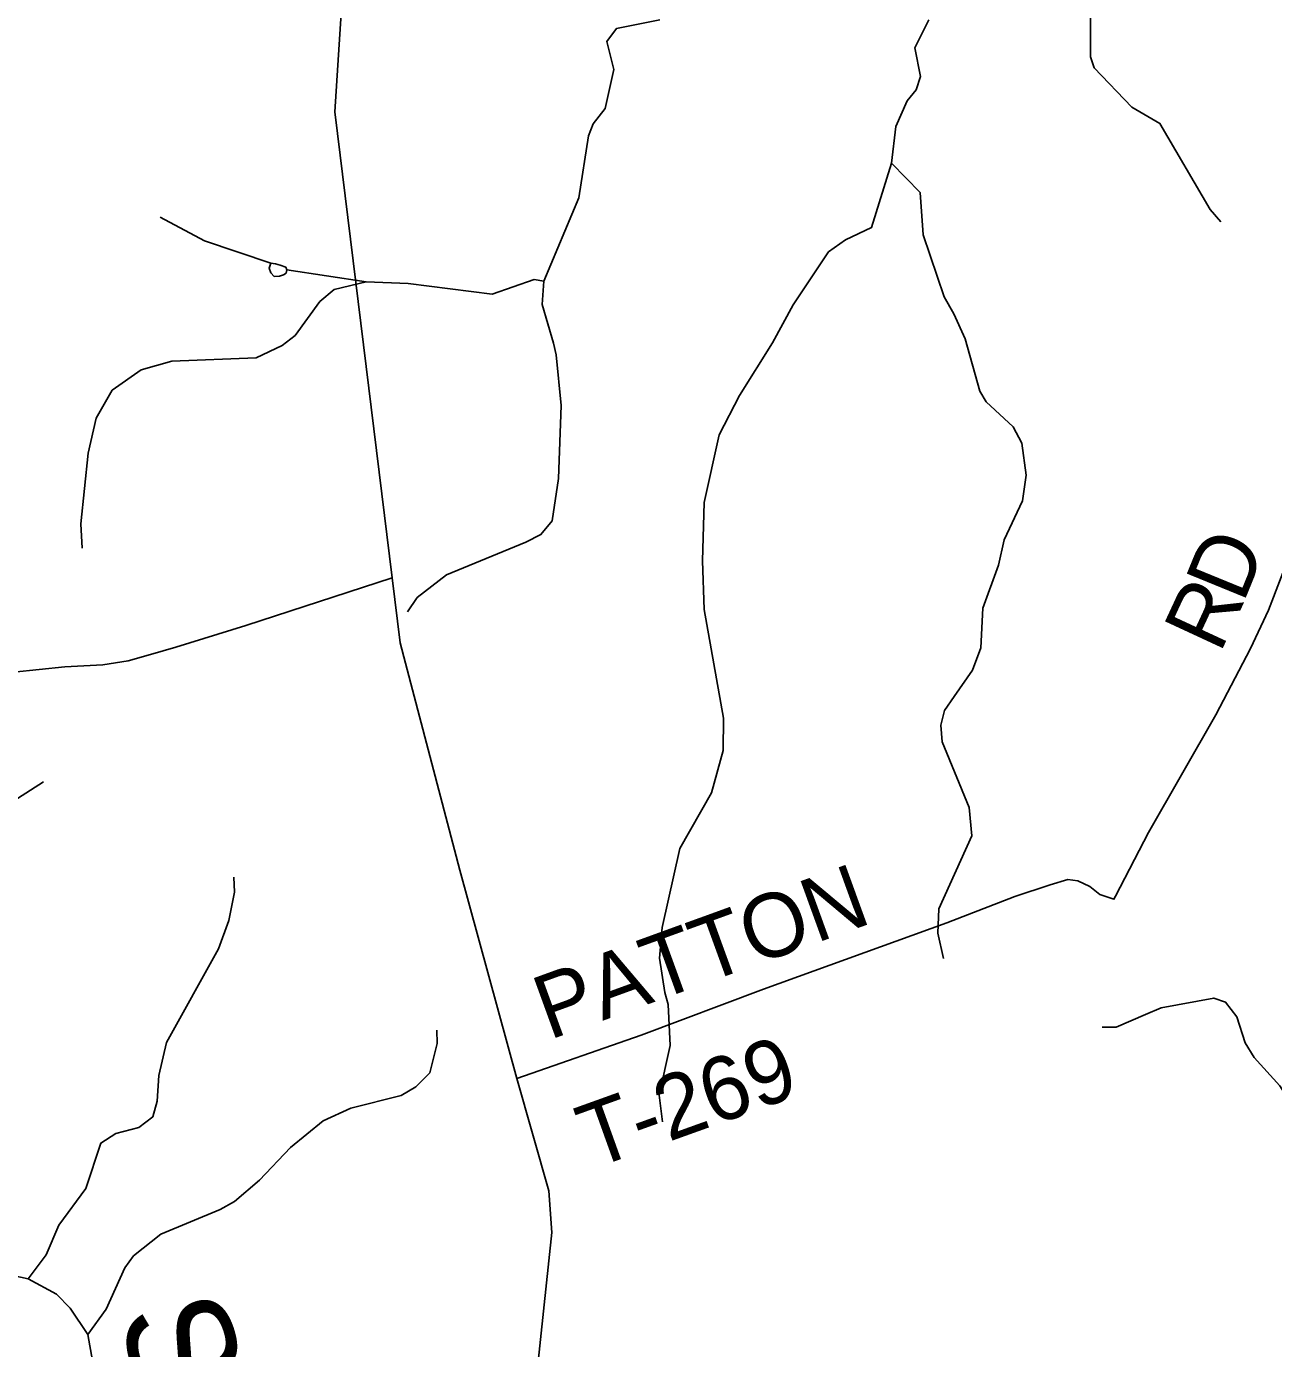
# Model space of a CAD drawing. Extents: x 1525783 to 1900577, y 218250 to 627376.
# Drawn here: x 1653092 to 1658967, y 423185 to 429415 of the extents above; entities that cross this region are included whole.
import ezdxf

# ---------------------------------------------------------------- set-up
doc = ezdxf.new("R2010")
doc.units = 0
for name, color, linetype in [('GM_X_Minor_Lake', 7, 'Continuous'), ('GM_X_Minor_River', 7, 'Continuous'), ('GM_X_Minor_River_Text', 7, 'Continuous'), ('GM_X_State_Route', 7, 'Continuous'), ('GM_X_Township_Road', 7, 'Continuous'), ('GM_X_Township_Road_Text', 7, 'Continuous')]:
    doc.layers.add(name, color=color, linetype=linetype)

msp = doc.modelspace()

# ---------------------------------------------------------------- linework, layer by layer
at = {"layer": 'GM_X_Minor_Lake'}
for points in [[(1654319, 428268.3), (1654313.3, 428280.7), (1654287.5, 428291.1), (1654265.6, 428297.5), (1654243.6, 428299.9), (1654235.2, 428276), (1654242.8, 428253.8), (1654258.5, 428237.5), (1654284.5, 428239.1), (1654302.7, 428244.8), (1654314.8, 428252.6)], [(1654314.8, 428252.6), (1654319, 428268.3)]]:
    msp.add_lwpolyline(points, dxfattribs=at)
at = {"layer": 'GM_X_Minor_River'}
for points in [[(1657832.2, 431128.7), (1657952.5, 430801.7), (1657990.9, 430602.5), (1657997.2, 430393.9), (1657942.1, 430224.3), (1657908.7, 430152.7), (1657901.5, 430084.6), (1658082.9, 429706.5), (1658104.6, 429577.8), (1658105.1, 429273), (1658122.2, 429220.5), (1658299, 429035), (1658431.7, 428958.5), (1658668.7, 428553.4), (1658719.7, 428494.3)], [(1656076.1, 429445.9), (1655871.2, 429405.3), (1655826, 429343.9), (1655859.7, 429213), (1655818.4, 429029.2), (1655761, 428955.9), (1655740, 428900.1), (1655694.6, 428608.1), (1655529.4, 428215.8), (1655521.4, 428105.6), (1655574.1, 427922.2), (1655587.2, 427867.8), (1655610.9, 427628.8), (1655598.7, 427286), (1655569, 427085.9), (1655515.8, 427020.7), (1655445.1, 426985.8), (1655069.9, 426831.7), (1654931.8, 426723.8), (1654886.6, 426656.3)], [(1657343.4, 429446.4), (1657277, 429315.1), (1657304.6, 429180.3), (1657283.4, 429116.5), (1657240.5, 429065.1), (1657188.2, 428943.6), (1657167.1, 428771.5), (1657302.7, 428632.8), (1657317.2, 428434), (1657416, 428141.5), (1657460.6, 428060.5), (1657514.5, 427943.3), (1657584.1, 427697.4), (1657613.3, 427646.8), (1657741.2, 427528.3), (1657781.9, 427451.3), (1657801.2, 427300.6), (1657785, 427180.5), (1657697.6, 426995.5), (1657671.4, 426877.6), (1657597.7, 426674.3), (1657588.3, 426487.9), (1657548.3, 426382.3), (1657462, 426257.4), (1657416.8, 426192), (1657399.5, 426122.1), (1657406.1, 426043.7), (1657532.6, 425734.7), (1657546.2, 425602.1), (1657389.8, 425257.8), (1657385.8, 425143.5), (1657411.6, 425022.7)], [(1657167.1, 428771.5), (1657073.5, 428468.2), (1656950.3, 428410.2), (1656871.2, 428353.4), (1656704.6, 428103.5), (1656607.2, 427924.7), (1656450.6, 427676.6), (1656355.2, 427491.7), (1656285.3, 427172), (1656276.3, 426897.4), (1656284.2, 426668.6), (1656375, 426155.6), (1656374.3, 426003.2), (1656318.6, 425803.5), (1656169.7, 425541.3), (1656086.9, 425169.7), (1656074.3, 425025.5), (1656099.4, 424862.6), (1656114.3, 424806.2), (1656124.9, 424613.4), (1656072.6, 424379.6), (1656088.3, 424253)], [(1654243.6, 428299.9), (1653931.2, 428405.5), (1653721, 428517.4)], [(1655529.4, 428215.8), (1655483.5, 428222.6), (1655286, 428153.8), (1654890.5, 428204.6), (1654692.5, 428212), (1654319, 428268.3)], [(1654692.5, 428212), (1654541.7, 428176.5), (1654474.6, 428119.5), (1654357.6, 427959), (1654296.6, 427911.9), (1654173.5, 427853.9), (1653776.8, 427838.6), (1653631.9, 427796.9), (1653496, 427701), (1653419.6, 427569.9), (1653382.5, 427404), (1653348.5, 427071.7), (1653354.4, 426957.3)], [(1652247, 424180.1), (1652312.4, 424361.5), (1652287.6, 424432.2), (1652264.7, 424601.1), (1652267.6, 424761.5), (1652302.2, 424905.3), (1652408.6, 425031.8), (1652458.2, 425119.2), (1652486.5, 425241.1), (1652508.5, 425353.1), (1652701, 425588.5), (1652802.4, 425661), (1653048.8, 425777.1), (1653172.3, 425855.2)], [(1653099.8, 423513.7), (1653184, 423626.6), (1653244.6, 423766), (1653371.8, 423940.3), (1653441.8, 424153.7), (1653512.7, 424198.7), (1653621.3, 424226.9), (1653686.3, 424277.9), (1653707.6, 424351.8), (1653715.8, 424472), (1653750.7, 424627.8), (1653996.9, 425068.9), (1654045.4, 425202.5), (1654071.8, 425336.4), (1654069.1, 425406.7)], [(1659643.5, 423231.6), (1659714.2, 423380.9), (1659250.6, 423980.5), (1659117.1, 424235.5), (1658996.4, 424424.1), (1658876.7, 424556.5), (1658833.9, 424625.4), (1658794.1, 424748.4), (1658741.3, 424817.5), (1658685.5, 424836.5), (1658438.5, 424790.6), (1658363.8, 424759.8), (1658226.6, 424699.9), (1658160.5, 424699.1)], [(1653381.4, 423252.2), (1653467.6, 423371), (1653555.3, 423566.1), (1653596.3, 423621.6), (1653724.3, 423723.7), (1654004.7, 423841.3), (1654071.4, 423878.2), (1654189.4, 423978.5), (1654336.3, 424132.5), (1654488.8, 424258.2), (1654620, 424318.2), (1654857.3, 424378.3), (1654926.1, 424419.2), (1654991.4, 424484.3), (1655025.9, 424622.1), (1655025.1, 424686.3)], [(1653403.2, 423127.4), (1653381.4, 423252.2), (1653297.5, 423376), (1653232.7, 423441.2), (1653099.8, 423513.7), (1652830.6, 423572.5)]]:
    msp.add_lwpolyline(points, dxfattribs=at)
at = {"layer": 'GM_X_State_Route'}
msp.add_lwpolyline([(1655460.8, 422723.9), (1655566.8, 423732), (1655552.5, 423929.2), (1655401.5, 424457.7), (1655132.9, 425439.2), (1654852.5, 426511), (1654815.3, 426817.4), (1654544.7, 429013.7), (1654603.4, 429918.4), (1654690.4, 430439.7), (1654768, 431280.8)], dxfattribs=at)
at = {"layer": 'GM_X_Township_Road'}
for points in [[(1658222.9, 425316.5), (1658378.8, 425617), (1658695, 426172), (1658858.2, 426484.6), (1658942.9, 426665), (1659175.1, 427266.3), (1659488.1, 428108.1), (1659663.7, 428547), (1659734.3, 428715.3), (1659767.1, 428952), (1659823.9, 429206.6), (1659902.9, 429473.2), (1659991.6, 429659.5), (1660114.6, 429930.1), (1660219.8, 430282.9), (1660281.9, 430444.7)], [(1653030.2, 426373.4), (1653272.6, 426397), (1653451, 426406.7), (1653571.2, 426426.5), (1653675.5, 426456.4), (1653795.8, 426490.3), (1654124.6, 426591.9), (1654815.3, 426817.4)], [(1655401.5, 424457.7), (1655987.9, 424662.7), (1656563.5, 424878.3), (1657427.9, 425191.5), (1657748.8, 425315.3), (1657915.3, 425371.1), (1657997.5, 425395), (1658045.5, 425388.9), (1658101.5, 425362.8), (1658149.5, 425324.5), (1658215.5, 425302.4), (1658222.9, 425316.5)]]:
    msp.add_lwpolyline(points, dxfattribs=at)

# ---------------------------------------------------------------- texts
at = {"layer": 'GM_X_Minor_River_Text'}
msp.add_text('South', height=500.05, rotation=288.45253, dxfattribs=at).set_placement((1653514.9, 423337.9))
at = {"layer": 'GM_X_Township_Road_Text'}
for s, rotation, p in [('D', 67.76514, (1658824.1, 426693.1)), ('R', 65.12127, (1658714.5, 426455.9)), ('PATTON', 19.96946, (1655554, 424638)), ('T-269', 19.76703, (1655760, 424030.5))]:
    msp.add_text(s, height=300, rotation=rotation, dxfattribs=at).set_placement(p)

doc.saveas('drawing.dxf')
